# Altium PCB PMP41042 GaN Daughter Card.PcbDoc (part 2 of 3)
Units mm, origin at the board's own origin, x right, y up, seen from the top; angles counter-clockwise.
Board outline 43.43 x 37.33 mm, 6 copper layers (Top Layer, MidLayer1, MidLayer2, MidLayer3, MidLayer4, Bottom Layer), stack 1.844 mm thick; 57 components, 55 nets, 240 pads, 238 vias.
Unrouted connection lines stored in the file: 15.
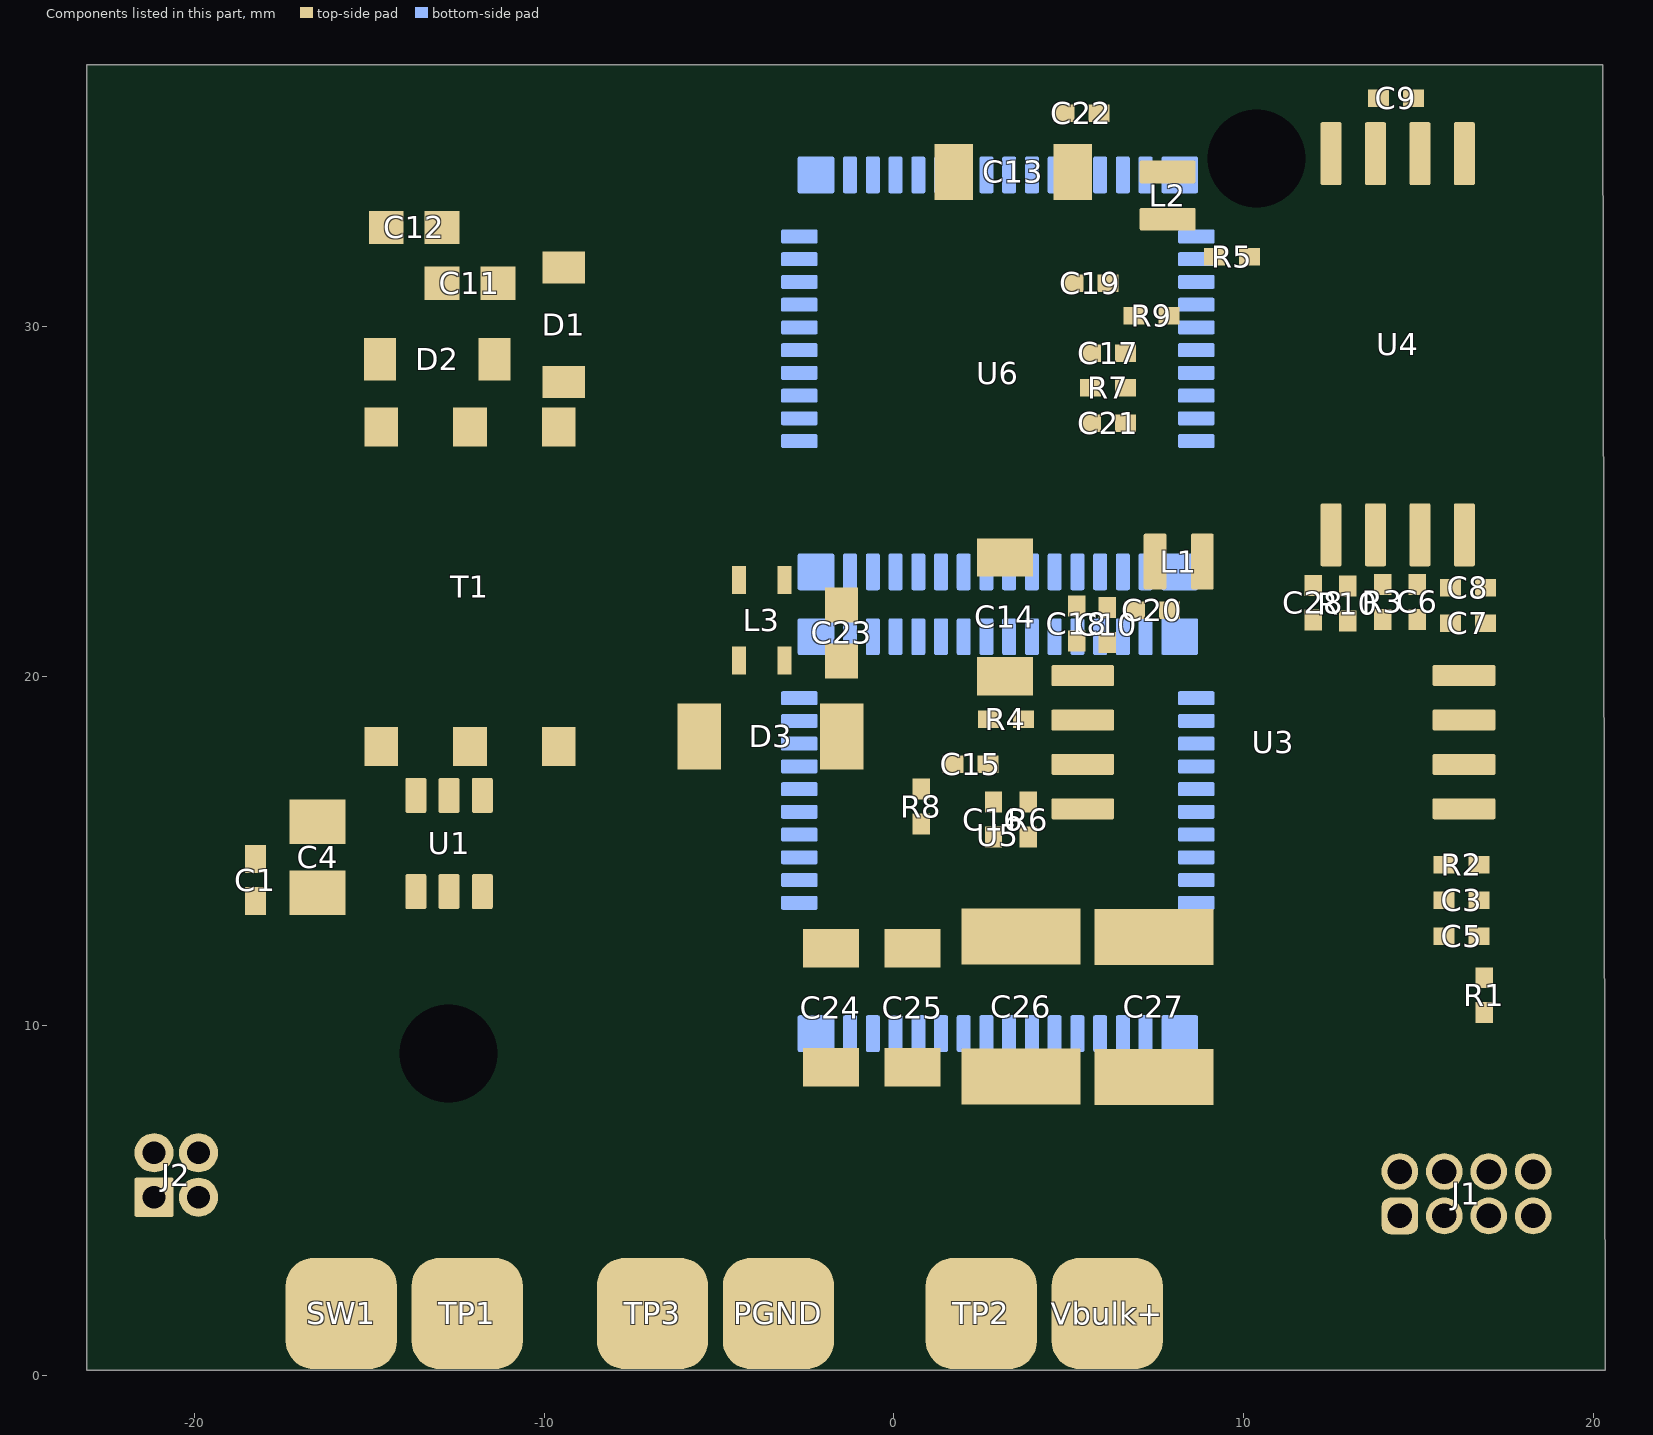
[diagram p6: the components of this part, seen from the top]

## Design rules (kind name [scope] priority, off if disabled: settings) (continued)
PolygonConnect PolygonConnect_46 [All vs IsNamedPolygon('PGND') Or  IsNamedPolygon('T200_4') Or  IsNamedPolygon('VBB') Or  IsNamedPolygon('SWNODE3') Or  IsNamedPolygon('LEG4_LS_DRV') Or  IsNamedPolygon('Iout_SNS') Or  IsNamedPolygon('SWNODE3') Or  IsNamedPolygon('T200_6') Or  IsNamedPolygon('SGND') Or  IsNamedPolygon('SIGNAL_LAYER_1_VBULK1_P106') Or  IsNamedPolygon('LEG3_HS_DRV') Or  IsNamedPolygon('TOP_LAYER_12VS_P126') Or  IsNamedPolygon('LEG4_HS_DRV') Or  IsNamedPolygon('SWNODE3') Or  IsNamedPolygon('SGND') Or  IsNamedPolygon('BOTTOM_LAYER_54V1_P128') Or  IsNamedPolygon('SGND') Or  IsNamedPolygon('Line') Or  IsNamedPolygon('TOP_LAYER_IOUT_SNS_P092') Or  IsNamedPolygon('C108_1') Or  IsNamedPolygon('D403_2') Or  IsNamedPolygon('SWNODE') Or  IsNamedPolygon('SIGNAL_LAYER_2_VBB_P094') Or  IsNamedPolygon('Vbulk') Or  IsNamedPolygon('D404_2') Or  IsNamedPolygon('VSR') Or  IsNamedPolygon('C108_1') Or  IsNamedPolygon('C108_1') Or  IsNamedPolygon('5Vp') Or  IsNamedPolygon('C108_1') Or  IsNamedPolygon('PGND') Or  IsNamedPolygon('D400_2') Or  IsNamedPolygon('SWNODE3') Or  IsNamedPolygon('Line') Or  IsNamedPolygon('C108_1') Or  IsNamedPolygon('TOP_LAYER_VBULK_P104') Or  IsNamedPolygon('Vbulk1') Or  IsNamedPolygon('T200_6') Or  IsNamedPolygon('T200_6') Or  IsNamedPolygon('SWNODE4') Or  IsNamedPolygon('C108_1') Or  IsNamedPolygon('D403_2') Or  IsNamedPolygon('PGND') Or  IsNamedPolygon('T200_4') Or  IsNamedPolygon('Line') Or  IsNamedPolygon('5Vs') Or  IsNamedPolygon('12Vp') Or  IsNamedPolygon('C102_1') Or  IsNamedPolygon('SGND') Or  IsNamedPolygon('TOP_LAYER_54V2_P048') Or  IsNamedPolygon('TOP_LAYER_54V1_P046') Or  IsNamedPolygon('SWNODE4') Or  IsNamedPolygon('ZCD') Or  IsNamedPolygon('SWNODE3') Or  IsNamedPolygon('SWNODE3') Or  IsNamedPolygon('BOTTOM_LAYER_NETC106_2_P030') Or  IsNamedPolygon('TOP_LAYER_54V2_P048') Or  IsNamedPolygon('T200_4') Or  IsNamedPolygon('SWNODE4') Or  IsNamedPolygon('SWNODE4') Or  IsNamedPolygon('SGND') Or  IsNamedPolygon('SGND') Or  IsNamedPolygon('SGND') Or  IsNamedPolygon('SWNODE4') Or  IsNamedPolygon('VSR') Or  IsNamedPolygon('SWNODE3') Or  IsNamedPolygon('SGND') Or  IsNamedPolygon('SGND') Or  IsNamedPolygon('SGND') Or  IsNamedPolygon('SGND') Or  IsNamedPolygon('SGND') Or  IsNamedPolygon('SGND') Or  IsNamedPolygon('BOTTOM_LAYER_54V1_P128') Or  IsNamedPolygon('SGND') Or  IsNamedPolygon('VSR') Or  IsNamedPolygon('C102_1') Or  IsNamedPolygon('C102_1') Or  IsNamedPolygon('C102_1') Or  IsNamedPolygon('C102_1') Or  IsNamedPolygon('C102_1') Or  IsNamedPolygon('ZCD') Or  IsNamedPolygon('PGND') Or  IsNamedPolygon('PGND') Or  IsNamedPolygon('Vbulk1') Or  IsNamedPolygon('Vbulk') Or  IsNamedPolygon('Vbulk1') Or  IsNamedPolygon('Vbulk1') Or  IsNamedPolygon('ZCD') Or  IsNamedPolygon('Neutral') Or  IsNamedPolygon('Neutral') Or  IsNamedPolygon('C106_2') Or  IsNamedPolygon('C106_2') Or  IsNamedPolygon('C106_2') Or  IsNamedPolygon('SWNODE') Or  IsNamedPolygon('Vbulk1') Or  IsNamedPolygon('Earth1') Or  IsNamedPolygon('Earth1') Or  IsNamedPolygon('Earth1') Or  IsNamedPolygon('Earth1') Or  IsNamedPolygon('Earth1') Or  IsNamedPolygon('Earth1') Or  IsNamedPolygon('ZCD') Or  IsNamedPolygon('VBB') Or  IsNamedPolygon('PGND') Or  IsNamedPolygon('D106_1') Or  IsNamedPolygon('PGND') Or  IsNamedPolygon('PGND') Or  IsNamedPolygon('D106_1') Or  IsNamedPolygon('Vbulk') Or  IsNamedPolygon('D106_1') Or  IsNamedPolygon('PGND') Or  IsNamedPolygon('VBB') Or  IsNamedPolygon('VBB') Or  IsNamedPolygon('PGND') Or  IsNamedPolygon('PGND') Or  IsNamedPolygon('PGND') Or  IsNamedPolygon('PGND') Or  IsNamedPolygon('PGND') Or  IsNamedPolygon('ZCD') Or  IsNamedPolygon('ZCD') Or  IsNamedPolygon('C412_2') Or  IsNamedPolygon('VBB') Or  IsNamedPolygon('PGND') Or  IsNamedPolygon('PGND') Or  IsNamedPolygon('PGND') Or  IsNamedPolygon('PGND') Or  IsNamedPolygon('PGND') Or  IsNamedPolygon('PGND') Or  IsNamedPolygon('PGND') Or  IsNamedPolygon('Vbulk') Or  IsNamedPolygon('D404_2') Or  IsNamedPolygon('PGND') Or  IsNamedPolygon('Iout_SNS') Or  IsNamedPolygon('54V2')] p14: connectstyle=Direct reliefconductorwidth=0.254 reliefentries=4 polygonreliefangle="90 Angle" airgapwidth=0.254
PolygonConnect PolygonConnect_45 [All vs IsNamedPolygon('Vbulk1') Or  IsNamedPolygon('TOP_LAYER_VBULK_P104') Or  IsNamedPolygon('SIGNAL_LAYER_1_VBULK1_P106') Or  IsNamedPolygon('Iout_SNS') Or  IsNamedPolygon('SIGNAL_LAYER_2_VBB_P094') Or  IsNamedPolygon('Line') Or  IsNamedPolygon('T200_4') Or  IsNamedPolygon('ZCD') Or  IsNamedPolygon('C108_1') Or  IsNamedPolygon('PGND') Or  IsNamedPolygon('BOTTOM_LAYER_NETC106_2_P030') Or  IsNamedPolygon('5Vp') Or  IsNamedPolygon('C108_1') Or  IsNamedPolygon('Line') Or  IsNamedPolygon('C102_1') Or  IsNamedPolygon('T200_4') Or  IsNamedPolygon('12Vp') Or  IsNamedPolygon('D403_2') Or  IsNamedPolygon('T200_6') Or  IsNamedPolygon('TOP_LAYER_54V1_P046') Or  IsNamedPolygon('TOP_LAYER_54V2_P048') Or  IsNamedPolygon('C108_1') Or  IsNamedPolygon('C108_1') Or  IsNamedPolygon('SWNODE3') Or  IsNamedPolygon('TOP_LAYER_54V2_P048') Or  IsNamedPolygon('PGND') Or  IsNamedPolygon('D403_2') Or  IsNamedPolygon('C108_1') Or  IsNamedPolygon('C108_1') Or  IsNamedPolygon('T200_6') Or  IsNamedPolygon('SGND') Or  IsNamedPolygon('SWNODE') Or  IsNamedPolygon('SGND') Or  IsNamedPolygon('SWNODE3') Or  IsNamedPolygon('BOTTOM_LAYER_54V1_P128') Or  IsNamedPolygon('C102_1') Or  IsNamedPolygon('SWNODE4') Or  IsNamedPolygon('C102_1') Or  IsNamedPolygon('SGND') Or  IsNamedPolygon('C102_1') Or  IsNamedPolygon('SGND') Or  IsNamedPolygon('VSR') Or  IsNamedPolygon('SGND') Or  IsNamedPolygon('SGND') Or  IsNamedPolygon('VSR') Or  IsNamedPolygon('SGND') Or  IsNamedPolygon('SWNODE4') Or  IsNamedPolygon('SGND') Or  IsNamedPolygon('SGND') Or  IsNamedPolygon('Vbulk1') Or  IsNamedPolygon('SGND') Or  IsNamedPolygon('PGND') Or  IsNamedPolygon('SGND') Or  IsNamedPolygon('PGND') Or  IsNamedPolygon('SWNODE3') Or  IsNamedPolygon('ZCD') Or  IsNamedPolygon('VSR') Or  IsNamedPolygon('C102_1') Or  IsNamedPolygon('SWNODE4') Or  IsNamedPolygon('C102_1') Or  IsNamedPolygon('SWNODE4') Or  IsNamedPolygon('SWNODE3') Or  IsNamedPolygon('PGND') Or  IsNamedPolygon('SGND') Or  IsNamedPolygon('D400_2') Or  IsNamedPolygon('SGND') Or  IsNamedPolygon('5Vs') Or  IsNamedPolygon('VBB') Or  IsNamedPolygon('T200_4') Or  IsNamedPolygon('T200_6') Or  IsNamedPolygon('SWNODE4') Or  IsNamedPolygon('LEG4_HS_DRV') Or  IsNamedPolygon('LEG4_LS_DRV') Or  IsNamedPolygon('LEG3_HS_DRV') Or  IsNamedPolygon('BOTTOM_LAYER_54V1_P128') Or  IsNamedPolygon('TOP_LAYER_12VS_P126') Or  IsNamedPolygon('Iout_SNS') Or  IsNamedPolygon('SWNODE3') Or  IsNamedPolygon('SWNODE3') Or  IsNamedPolygon('SWNODE3') Or  IsNamedPolygon('VBB') Or  IsNamedPolygon('Line') Or  IsNamedPolygon('D404_2') Or  IsNamedPolygon('SGND') Or  IsNamedPolygon('VBB') Or  IsNamedPolygon('VBB') Or  IsNamedPolygon('PGND') Or  IsNamedPolygon('PGND') Or  IsNamedPolygon('PGND') Or  IsNamedPolygon('PGND') Or  IsNamedPolygon('PGND') Or  IsNamedPolygon('ZCD') Or  IsNamedPolygon('ZCD') Or  IsNamedPolygon('C412_2') Or  IsNamedPolygon('VBB') Or  IsNamedPolygon('PGND') Or  IsNamedPolygon('PGND') Or  IsNamedPolygon('PGND') Or  IsNamedPolygon('PGND') Or  IsNamedPolygon('PGND') Or  IsNamedPolygon('PGND') Or  IsNamedPolygon('PGND') Or  IsNamedPolygon('VBB') Or  IsNamedPolygon('D404_2') Or  IsNamedPolygon('VBB') Or  IsNamedPolygon('Vbulk1') Or  IsNamedPolygon('Vbulk1') Or  IsNamedPolygon('ZCD') Or  IsNamedPolygon('Neutral') Or  IsNamedPolygon('Neutral') Or  IsNamedPolygon('C106_2') Or  IsNamedPolygon('C106_2') Or  IsNamedPolygon('C106_2') Or  IsNamedPolygon('SWNODE') Or  IsNamedPolygon('Vbulk1') Or  IsNamedPolygon('Earth1') Or  IsNamedPolygon('Earth1') Or  IsNamedPolygon('Earth1') Or  IsNamedPolygon('Earth1') Or  IsNamedPolygon('Earth1') Or  IsNamedPolygon('Earth1') Or  IsNamedPolygon('ZCD') Or  IsNamedPolygon('VBB') Or  IsNamedPolygon('PGND') Or  IsNamedPolygon('D106_1') Or  IsNamedPolygon('PGND') Or  IsNamedPolygon('PGND') Or  IsNamedPolygon('D106_1') Or  IsNamedPolygon('VBB') Or  IsNamedPolygon('D106_1') Or  IsNamedPolygon('PGND')] p15: connectstyle=Direct reliefconductorwidth=0.254 reliefentries=4 polygonreliefangle="90 Angle" airgapwidth=0.254
PolygonConnect PolygonConnect_44 [All vs IsNamedPolygon('Earth1') Or  IsNamedPolygon('Vbulk1') Or  IsNamedPolygon('Vbulk1') Or  IsNamedPolygon('VBB') Or  IsNamedPolygon('Vbulk1') Or  IsNamedPolygon('ZCD') Or  IsNamedPolygon('VBB') Or  IsNamedPolygon('PGND') Or  IsNamedPolygon('C412_2') Or  IsNamedPolygon('ZCD') Or  IsNamedPolygon('D106_1') Or  IsNamedPolygon('D106_1') Or  IsNamedPolygon('ZCD') Or  IsNamedPolygon('PGND') Or  IsNamedPolygon('PGND') Or  IsNamedPolygon('ZCD') Or  IsNamedPolygon('VBB') Or  IsNamedPolygon('PGND') Or  IsNamedPolygon('VBB') Or  IsNamedPolygon('PGND') Or  IsNamedPolygon('D106_1') Or  IsNamedPolygon('PGND') Or  IsNamedPolygon('PGND') Or  IsNamedPolygon('PGND') Or  IsNamedPolygon('VBB') Or  IsNamedPolygon('PGND') Or  IsNamedPolygon('PGND') Or  IsNamedPolygon('C102_1') Or  IsNamedPolygon('ZCD') Or  IsNamedPolygon('C102_1') Or  IsNamedPolygon('C102_1') Or  IsNamedPolygon('C102_1') Or  IsNamedPolygon('PGND') Or  IsNamedPolygon('C102_1') Or  IsNamedPolygon('Line') Or  IsNamedPolygon('T200_4') Or  IsNamedPolygon('T200_4') Or  IsNamedPolygon('SIGNAL_LAYER_1_VBULK1_P106') Or  IsNamedPolygon('TOP_LAYER_VBULK_P104') Or  IsNamedPolygon('T200_4') Or  IsNamedPolygon('SGND') Or  IsNamedPolygon('T200_6') Or  IsNamedPolygon('C108_1') Or  IsNamedPolygon('SWNODE3') Or  IsNamedPolygon('SWNODE') Or  IsNamedPolygon('SWNODE3') Or  IsNamedPolygon('LEG3_HS_DRV') Or  IsNamedPolygon('BOTTOM_LAYER_NETC106_2_P030') Or  IsNamedPolygon('C102_1') Or  IsNamedPolygon('SWNODE4') Or  IsNamedPolygon('SIGNAL_LAYER_2_VBB_P094') Or  IsNamedPolygon('SGND') Or  IsNamedPolygon('VSR') Or  IsNamedPolygon('C108_1') Or  IsNamedPolygon('BOTTOM_LAYER_54V1_P128') Or  IsNamedPolygon('TOP_LAYER_54V2_P048') Or  IsNamedPolygon('TOP_LAYER_54V1_P046') Or  IsNamedPolygon('C108_1') Or  IsNamedPolygon('D403_2') Or  IsNamedPolygon('ZCD') Or  IsNamedPolygon('PGND') Or  IsNamedPolygon('SWNODE3') Or  IsNamedPolygon('Line') Or  IsNamedPolygon('D400_2') Or  IsNamedPolygon('SGND') Or  IsNamedPolygon('PGND') Or  IsNamedPolygon('SGND') Or  IsNamedPolygon('LEG4_HS_DRV') Or  IsNamedPolygon('SWNODE3') Or  IsNamedPolygon('5Vs') Or  IsNamedPolygon('SWNODE4') Or  IsNamedPolygon('SGND') Or  IsNamedPolygon('SGND') Or  IsNamedPolygon('C108_1') Or  IsNamedPolygon('5Vp') Or  IsNamedPolygon('12Vp') Or  IsNamedPolygon('Iout_SNS') Or  IsNamedPolygon('D404_2') Or  IsNamedPolygon('SGND') Or  IsNamedPolygon('T200_6') Or  IsNamedPolygon('TOP_LAYER_54V2_P048') Or  IsNamedPolygon('SGND') Or  IsNamedPolygon('SWNODE3') Or  IsNamedPolygon('SWNODE4') Or  IsNamedPolygon('Iout_SNS') Or  IsNamedPolygon('C108_1') Or  IsNamedPolygon('BOTTOM_LAYER_54V1_P128') Or  IsNamedPolygon('SWNODE3') Or  IsNamedPolygon('LEG4_LS_DRV') Or  IsNamedPolygon('SGND') Or  IsNamedPolygon('SWNODE4') Or  IsNamedPolygon('T200_6') Or  IsNamedPolygon('TOP_LAYER_12VS_P126') Or  IsNamedPolygon('Line') Or  IsNamedPolygon('Vbulk1') Or  IsNamedPolygon('SWNODE3') Or  IsNamedPolygon('SGND') Or  IsNamedPolygon('VBB') Or  IsNamedPolygon('SGND') Or  IsNamedPolygon('SGND') Or  IsNamedPolygon('SWNODE4') Or  IsNamedPolygon('PGND') Or  IsNamedPolygon('D403_2') Or  IsNamedPolygon('VSR') Or  IsNamedPolygon('SGND') Or  IsNamedPolygon('SGND') Or  IsNamedPolygon('VBB') Or  IsNamedPolygon('C108_1') Or  IsNamedPolygon('Earth1') Or  IsNamedPolygon('Earth1') Or  IsNamedPolygon('VSR') Or  IsNamedPolygon('C106_2') Or  IsNamedPolygon('Vbulk1') Or  IsNamedPolygon('C106_2') Or  IsNamedPolygon('C106_2') Or  IsNamedPolygon('Earth1') Or  IsNamedPolygon('SWNODE') Or  IsNamedPolygon('Neutral') Or  IsNamedPolygon('Earth1') Or  IsNamedPolygon('Earth1') Or  IsNamedPolygon('Neutral')] p16: connectstyle=Direct reliefconductorwidth=0.254 reliefentries=4 polygonreliefangle="90 Angle" airgapwidth=0.254
PolygonConnect PolygonConnect_43 [All vs IsNamedPolygon('SWNODE') Or  IsNamedPolygon('D403_2') Or  IsNamedPolygon('D403_2') Or  IsNamedPolygon('PGND') Or  IsNamedPolygon('BOTTOM_LAYER_NETC106_2_P030') Or  IsNamedPolygon('C102_1') Or  IsNamedPolygon('SGND') Or  IsNamedPolygon('TOP_LAYER_54V1_P046') Or  IsNamedPolygon('TOP_LAYER_54V2_P048') Or  IsNamedPolygon('TOP_LAYER_54V2_P048') Or  IsNamedPolygon('C108_1') Or  IsNamedPolygon('C108_1') Or  IsNamedPolygon('C108_1') Or  IsNamedPolygon('C108_1') Or  IsNamedPolygon('C108_1') Or  IsNamedPolygon('C108_1') Or  IsNamedPolygon('PGND') Or  IsNamedPolygon('ZCD') Or  IsNamedPolygon('Line') Or  IsNamedPolygon('5Vp') Or  IsNamedPolygon('12Vp') Or  IsNamedPolygon('T200_4') Or  IsNamedPolygon('T200_6') Or  IsNamedPolygon('SWNODE3') Or  IsNamedPolygon('T200_4') Or  IsNamedPolygon('T200_6') Or  IsNamedPolygon('SWNODE4') Or  IsNamedPolygon('VSR') Or  IsNamedPolygon('Iout_SNS') Or  IsNamedPolygon('SIGNAL_LAYER_2_VBB_P094') Or  IsNamedPolygon('Vbulk1') Or  IsNamedPolygon('TOP_LAYER_VBULK_P104') Or  IsNamedPolygon('SIGNAL_LAYER_1_VBULK1_P106') Or  IsNamedPolygon('Line') Or  IsNamedPolygon('Line') Or  IsNamedPolygon('D404_2') Or  IsNamedPolygon('VBB') Or  IsNamedPolygon('D400_2') Or  IsNamedPolygon('SGND') Or  IsNamedPolygon('PGND') Or  IsNamedPolygon('TOP_LAYER_12VS_P126') Or  IsNamedPolygon('BOTTOM_LAYER_54V1_P128') Or  IsNamedPolygon('LEG3_HS_DRV') Or  IsNamedPolygon('LEG4_LS_DRV') Or  IsNamedPolygon('LEG4_HS_DRV') Or  IsNamedPolygon('SWNODE4') Or  IsNamedPolygon('SWNODE3') Or  IsNamedPolygon('T200_6') Or  IsNamedPolygon('T200_4') Or  IsNamedPolygon('VBB') Or  IsNamedPolygon('5Vs') Or  IsNamedPolygon('SGND') Or  IsNamedPolygon('Iout_SNS') Or  IsNamedPolygon('SGND') Or  IsNamedPolygon('SWNODE3') Or  IsNamedPolygon('SWNODE3') Or  IsNamedPolygon('SWNODE3') Or  IsNamedPolygon('SWNODE3') Or  IsNamedPolygon('SGND') Or  IsNamedPolygon('SGND') Or  IsNamedPolygon('SGND') Or  IsNamedPolygon('SWNODE4') Or  IsNamedPolygon('SWNODE4') Or  IsNamedPolygon('SWNODE4') Or  IsNamedPolygon('VSR') Or  IsNamedPolygon('SWNODE3') Or  IsNamedPolygon('SGND') Or  IsNamedPolygon('SGND') Or  IsNamedPolygon('SGND') Or  IsNamedPolygon('SGND') Or  IsNamedPolygon('SGND') Or  IsNamedPolygon('SGND') Or  IsNamedPolygon('BOTTOM_LAYER_54V1_P128') Or  IsNamedPolygon('SGND') Or  IsNamedPolygon('VSR') Or  IsNamedPolygon('C102_1') Or  IsNamedPolygon('C102_1') Or  IsNamedPolygon('C102_1') Or  IsNamedPolygon('C102_1') Or  IsNamedPolygon('C102_1') Or  IsNamedPolygon('ZCD') Or  IsNamedPolygon('PGND') Or  IsNamedPolygon('PGND') Or  IsNamedPolygon('Vbulk1') Or  IsNamedPolygon('VBB') Or  IsNamedPolygon('Vbulk1') Or  IsNamedPolygon('Vbulk1') Or  IsNamedPolygon('ZCD') Or  IsNamedPolygon('Neutral') Or  IsNamedPolygon('Neutral') Or  IsNamedPolygon('C106_2') Or  IsNamedPolygon('C106_2') Or  IsNamedPolygon('C106_2') Or  IsNamedPolygon('SWNODE') Or  IsNamedPolygon('Vbulk1') Or  IsNamedPolygon('Earth1') Or  IsNamedPolygon('Earth1') Or  IsNamedPolygon('Earth1') Or  IsNamedPolygon('Earth1') Or  IsNamedPolygon('Earth1') Or  IsNamedPolygon('Earth1') Or  IsNamedPolygon('ZCD') Or  IsNamedPolygon('VBB') Or  IsNamedPolygon('PGND') Or  IsNamedPolygon('D106_1') Or  IsNamedPolygon('PGND') Or  IsNamedPolygon('PGND') Or  IsNamedPolygon('D106_1') Or  IsNamedPolygon('VBB') Or  IsNamedPolygon('D106_1') Or  IsNamedPolygon('PGND') Or  IsNamedPolygon('VBB') Or  IsNamedPolygon('VBB') Or  IsNamedPolygon('PGND') Or  IsNamedPolygon('PGND') Or  IsNamedPolygon('PGND') Or  IsNamedPolygon('PGND') Or  IsNamedPolygon('PGND')] p17: connectstyle=Direct reliefconductorwidth=0.254 reliefentries=4 polygonreliefangle="90 Angle" airgapwidth=0.254
PolygonConnect PolygonConnect_42 [All vs IsNamedPolygon('Neutral') Or  IsNamedPolygon('Earth1') Or  IsNamedPolygon('Earth1') Or  IsNamedPolygon('D404_2') Or  IsNamedPolygon('Line') Or  IsNamedPolygon('SIGNAL_LAYER_1_VBULK1_P106') Or  IsNamedPolygon('Line') Or  IsNamedPolygon('C102_1') Or  IsNamedPolygon('SWNODE3') Or  IsNamedPolygon('SWNODE3') Or  IsNamedPolygon('SWNODE') Or  IsNamedPolygon('5Vp') Or  IsNamedPolygon('T200_6') Or  IsNamedPolygon('SWNODE3') Or  IsNamedPolygon('SGND') Or  IsNamedPolygon('SWNODE3') Or  IsNamedPolygon('VSR') Or  IsNamedPolygon('C108_1') Or  IsNamedPolygon('SWNODE3') Or  IsNamedPolygon('TOP_LAYER_12VS_P126') Or  IsNamedPolygon('SGND') Or  IsNamedPolygon('SGND') Or  IsNamedPolygon('SGND') Or  IsNamedPolygon('T200_6') Or  IsNamedPolygon('SWNODE4') Or  IsNamedPolygon('C108_1') Or  IsNamedPolygon('C106_2') Or  IsNamedPolygon('SGND') Or  IsNamedPolygon('Neutral') Or  IsNamedPolygon('SIGNAL_LAYER_2_VBB_P094') Or  IsNamedPolygon('Vbulk1') Or  IsNamedPolygon('SGND') Or  IsNamedPolygon('SGND') Or  IsNamedPolygon('TOP_LAYER_54V1_P046') Or  IsNamedPolygon('TOP_LAYER_54V2_P048') Or  IsNamedPolygon('TOP_LAYER_54V2_P048') Or  IsNamedPolygon('C102_1') Or  IsNamedPolygon('SGND') Or  IsNamedPolygon('T200_4') Or  IsNamedPolygon('12Vp') Or  IsNamedPolygon('SGND') Or  IsNamedPolygon('D400_2') Or  IsNamedPolygon('LEG3_HS_DRV') Or  IsNamedPolygon('LEG4_LS_DRV') Or  IsNamedPolygon('T200_4') Or  IsNamedPolygon('BOTTOM_LAYER_54V1_P128') Or  IsNamedPolygon('SGND') Or  IsNamedPolygon('VBB') Or  IsNamedPolygon('SWNODE4') Or  IsNamedPolygon('SWNODE4') Or  IsNamedPolygon('SWNODE4') Or  IsNamedPolygon('VSR') Or  IsNamedPolygon('Iout_SNS') Or  IsNamedPolygon('VBB') Or  IsNamedPolygon('PGND') Or  IsNamedPolygon('Line') Or  IsNamedPolygon('ZCD') Or  IsNamedPolygon('D403_2') Or  IsNamedPolygon('SWNODE3') Or  IsNamedPolygon('Vbulk1') Or  IsNamedPolygon('ZCD') Or  IsNamedPolygon('LEG4_HS_DRV') Or  IsNamedPolygon('BOTTOM_LAYER_54V1_P128') Or  IsNamedPolygon('VBB') Or  IsNamedPolygon('PGND') Or  IsNamedPolygon('ZCD') Or  IsNamedPolygon('ZCD') Or  IsNamedPolygon('Earth1') Or  IsNamedPolygon('VBB') Or  IsNamedPolygon('PGND') Or  IsNamedPolygon('PGND') Or  IsNamedPolygon('Vbulk1') Or  IsNamedPolygon('SWNODE') Or  IsNamedPolygon('C106_2') Or  IsNamedPolygon('C106_2') Or  IsNamedPolygon('C108_1') Or  IsNamedPolygon('SWNODE3') Or  IsNamedPolygon('SWNODE4') Or  IsNamedPolygon('Vbulk1') Or  IsNamedPolygon('SGND') Or  IsNamedPolygon('C102_1') Or  IsNamedPolygon('BOTTOM_LAYER_NETC106_2_P030') Or  IsNamedPolygon('Earth1') Or  IsNamedPolygon('Earth1') Or  IsNamedPolygon('Vbulk1') Or  IsNamedPolygon('Earth1') Or  IsNamedPolygon('T200_6') Or  IsNamedPolygon('T200_4') Or  IsNamedPolygon('C102_1') Or  IsNamedPolygon('C102_1') Or  IsNamedPolygon('C102_1') Or  IsNamedPolygon('VBB') Or  IsNamedPolygon('5Vs') Or  IsNamedPolygon('SGND') Or  IsNamedPolygon('Iout_SNS') Or  IsNamedPolygon('C108_1') Or  IsNamedPolygon('C108_1') Or  IsNamedPolygon('C108_1') Or  IsNamedPolygon('PGND') Or  IsNamedPolygon('D403_2') Or  IsNamedPolygon('PGND') Or  IsNamedPolygon('SGND') Or  IsNamedPolygon('SGND') Or  IsNamedPolygon('VSR')] p18: connectstyle=Direct reliefconductorwidth=0.254 reliefentries=4 polygonreliefangle="90 Angle" airgapwidth=0.254
PolygonConnect PolygonConnect_41 [All vs IsNamedPolygon('VBB') Or  IsNamedPolygon('SWNODE3') Or  IsNamedPolygon('T200_4') Or  IsNamedPolygon('Earth1') Or  IsNamedPolygon('BOTTOM_LAYER_54V1_P128') Or  IsNamedPolygon('SGND') Or  IsNamedPolygon('TOP_LAYER_12VS_P126') Or  IsNamedPolygon('C102_1') Or  IsNamedPolygon('VSR') Or  IsNamedPolygon('Earth1') Or  IsNamedPolygon('Neutral') Or  IsNamedPolygon('Vbulk1') Or  IsNamedPolygon('SWNODE4') Or  IsNamedPolygon('C106_2') Or  IsNamedPolygon('PGND') Or  IsNamedPolygon('SGND') Or  IsNamedPolygon('VBB') Or  IsNamedPolygon('PGND') Or  IsNamedPolygon('LEG4_LS_DRV') Or  IsNamedPolygon('C102_1') Or  IsNamedPolygon('SWNODE4') Or  IsNamedPolygon('C106_2') Or  IsNamedPolygon('Vbulk1') Or  IsNamedPolygon('C102_1') Or  IsNamedPolygon('BOTTOM_LAYER_54V1_P128') Or  IsNamedPolygon('LEG3_HS_DRV') Or  IsNamedPolygon('SGND') Or  IsNamedPolygon('SGND') Or  IsNamedPolygon('Earth1') Or  IsNamedPolygon('SGND') Or  IsNamedPolygon('SGND') Or  IsNamedPolygon('5Vs') Or  IsNamedPolygon('LEG4_HS_DRV') Or  IsNamedPolygon('Earth1') Or  IsNamedPolygon('SGND') Or  IsNamedPolygon('SWNODE3') Or  IsNamedPolygon('Iout_SNS') Or  IsNamedPolygon('ZCD') Or  IsNamedPolygon('Earth1') Or  IsNamedPolygon('VSR') Or  IsNamedPolygon('C102_1') Or  IsNamedPolygon('C102_1') Or  IsNamedPolygon('Vbulk1') Or  IsNamedPolygon('C106_2') Or  IsNamedPolygon('ZCD') Or  IsNamedPolygon('SWNODE3') Or  IsNamedPolygon('SWNODE3') Or  IsNamedPolygon('Vbulk1') Or  IsNamedPolygon('SWNODE4') Or  IsNamedPolygon('Neutral') Or  IsNamedPolygon('SWNODE3') Or  IsNamedPolygon('SWNODE4') Or  IsNamedPolygon('Earth1') Or  IsNamedPolygon('D400_2') Or  IsNamedPolygon('SGND') Or  IsNamedPolygon('SGND') Or  IsNamedPolygon('SGND') Or  IsNamedPolygon('SWNODE') Or  IsNamedPolygon('VSR') Or  IsNamedPolygon('SGND') Or  IsNamedPolygon('SIGNAL_LAYER_1_VBULK1_P106') Or  IsNamedPolygon('SGND') Or  IsNamedPolygon('T200_6') Or  IsNamedPolygon('SWNODE4') Or  IsNamedPolygon('VBB') Or  IsNamedPolygon('T200_6') Or  IsNamedPolygon('Line') Or  IsNamedPolygon('Iout_SNS') Or  IsNamedPolygon('Vbulk1') Or  IsNamedPolygon('VBB') Or  IsNamedPolygon('SIGNAL_LAYER_2_VBB_P094') Or  IsNamedPolygon('SGND') Or  IsNamedPolygon('D404_2') Or  IsNamedPolygon('SWNODE3') Or  IsNamedPolygon('Line') Or  IsNamedPolygon('PGND') Or  IsNamedPolygon('TOP_LAYER_54V2_P048') Or  IsNamedPolygon('TOP_LAYER_54V1_P046') Or  IsNamedPolygon('TOP_LAYER_54V2_P048') Or  IsNamedPolygon('C108_1') Or  IsNamedPolygon('BOTTOM_LAYER_NETC106_2_P030') Or  IsNamedPolygon('D403_2') Or  IsNamedPolygon('T200_4') Or  IsNamedPolygon('Line') Or  IsNamedPolygon('PGND') Or  IsNamedPolygon('SWNODE3') Or  IsNamedPolygon('ZCD') Or  IsNamedPolygon('SWNODE') Or  IsNamedPolygon('D403_2') Or  IsNamedPolygon('C108_1') Or  IsNamedPolygon('C102_1') Or  IsNamedPolygon('C108_1') Or  IsNamedPolygon('PGND') Or  IsNamedPolygon('C108_1') Or  IsNamedPolygon('C108_1') Or  IsNamedPolygon('5Vp') Or  IsNamedPolygon('T200_4') Or  IsNamedPolygon('12Vp') Or  IsNamedPolygon('T200_6') Or  IsNamedPolygon('C108_1') Or  IsNamedPolygon('SGND')] p19: connectstyle=Direct reliefconductorwidth=0.254 reliefentries=4 polygonreliefangle="90 Angle" airgapwidth=0.254
PolygonConnect PolygonConnect_40 [All vs IsNamedPolygon('Neutral')] p20: connectstyle=Direct reliefconductorwidth=0.254 reliefentries=4 polygonreliefangle="90 Angle" airgapwidth=0.254
PolygonConnect PolygonConnect_39 [All vs IsNamedPolygon('12Vp')] p21: connectstyle=Direct reliefconductorwidth=0.254 reliefentries=4 polygonreliefangle="90 Angle" airgapwidth=0.254
PolygonConnect PolygonConnect_38 [All vs IsNamedPolygon('SWNODE') Or  IsNamedPolygon('D403_2') Or  IsNamedPolygon('D403_2') Or  IsNamedPolygon('PGND') Or  IsNamedPolygon('BOTTOM_LAYER_NETC106_2_P030') Or  IsNamedPolygon('C102_1') Or  IsNamedPolygon('SGND') Or  IsNamedPolygon('TOP_LAYER_54V1_P046') Or  IsNamedPolygon('TOP_LAYER_54V2_P048') Or  IsNamedPolygon('TOP_LAYER_54V2_P048') Or  IsNamedPolygon('C108_1') Or  IsNamedPolygon('C108_1') Or  IsNamedPolygon('C108_1') Or  IsNamedPolygon('C108_1') Or  IsNamedPolygon('C108_1') Or  IsNamedPolygon('C108_1') Or  IsNamedPolygon('PGND') Or  IsNamedPolygon('ZCD') Or  IsNamedPolygon('Line') Or  IsNamedPolygon('5Vp') Or  IsNamedPolygon('12Vp') Or  IsNamedPolygon('T200_4') Or  IsNamedPolygon('T200_6') Or  IsNamedPolygon('SWNODE3') Or  IsNamedPolygon('T200_4') Or  IsNamedPolygon('T200_6') Or  IsNamedPolygon('SWNODE4') Or  IsNamedPolygon('VSR') Or  IsNamedPolygon('Iout_SNS') Or  IsNamedPolygon('SIGNAL_LAYER_2_VBB_P094') Or  IsNamedPolygon('Vbulk1') Or  IsNamedPolygon('VBB') Or  IsNamedPolygon('SIGNAL_LAYER_1_VBULK1_P106') Or  IsNamedPolygon('Line') Or  IsNamedPolygon('Line') Or  IsNamedPolygon('Line') Or  IsNamedPolygon('D404_2') Or  IsNamedPolygon('VBB') Or  IsNamedPolygon('D400_2') Or  IsNamedPolygon('SGND') Or  IsNamedPolygon('PGND') Or  IsNamedPolygon('TOP_LAYER_12VS_P126') Or  IsNamedPolygon('BOTTOM_LAYER_54V1_P128') Or  IsNamedPolygon('LEG3_HS_DRV') Or  IsNamedPolygon('LEG4_LS_DRV') Or  IsNamedPolygon('LEG4_HS_DRV') Or  IsNamedPolygon('SWNODE4') Or  IsNamedPolygon('SWNODE3') Or  IsNamedPolygon('T200_6') Or  IsNamedPolygon('T200_4') Or  IsNamedPolygon('VBB') Or  IsNamedPolygon('5Vs') Or  IsNamedPolygon('SGND') Or  IsNamedPolygon('Iout_SNS') Or  IsNamedPolygon('SGND') Or  IsNamedPolygon('SWNODE3') Or  IsNamedPolygon('SWNODE3') Or  IsNamedPolygon('SWNODE3') Or  IsNamedPolygon('SWNODE3') Or  IsNamedPolygon('SGND') Or  IsNamedPolygon('SGND') Or  IsNamedPolygon('SGND') Or  IsNamedPolygon('SWNODE4') Or  IsNamedPolygon('SWNODE4') Or  IsNamedPolygon('SWNODE4') Or  IsNamedPolygon('VSR') Or  IsNamedPolygon('SWNODE3') Or  IsNamedPolygon('SGND') Or  IsNamedPolygon('SGND') Or  IsNamedPolygon('SGND') Or  IsNamedPolygon('SGND') Or  IsNamedPolygon('SGND') Or  IsNamedPolygon('SGND') Or  IsNamedPolygon('BOTTOM_LAYER_54V1_P128') Or  IsNamedPolygon('SGND') Or  IsNamedPolygon('VSR') Or  IsNamedPolygon('C102_1') Or  IsNamedPolygon('C102_1') Or  IsNamedPolygon('C102_1') Or  IsNamedPolygon('C102_1') Or  IsNamedPolygon('C102_1') Or  IsNamedPolygon('ZCD') Or  IsNamedPolygon('PGND') Or  IsNamedPolygon('PGND') Or  IsNamedPolygon('Vbulk1') Or  IsNamedPolygon('VBB') Or  IsNamedPolygon('Vbulk1') Or  IsNamedPolygon('Vbulk1') Or  IsNamedPolygon('ZCD') Or  IsNamedPolygon('Neutral') Or  IsNamedPolygon('Neutral')] p22: connectstyle=Direct reliefconductorwidth=0.254 reliefentries=4 polygonreliefangle="90 Angle" airgapwidth=0.254
PolygonConnect PolygonConnect_37 [All vs IsNamedPolygon('SGND') Or  IsNamedPolygon('SWNODE4') Or  IsNamedPolygon('5Vp') Or  IsNamedPolygon('SWNODE4') Or  IsNamedPolygon('VBB') Or  IsNamedPolygon('Line') Or  IsNamedPolygon('SGND') Or  IsNamedPolygon('SIGNAL_LAYER_2_C102_1_P032') Or  IsNamedPolygon('TOP_LAYER_54V2_P048') Or  IsNamedPolygon('ZCD') Or  IsNamedPolygon('PGND') Or  IsNamedPolygon('SIGNAL_LAYER_2_VBB_P094') Or  IsNamedPolygon('Line') Or  IsNamedPolygon('Line') Or  IsNamedPolygon('D404_2') Or  IsNamedPolygon('PGND') Or  IsNamedPolygon('SIGNAL_LAYER_1_ZCD_P108') Or  IsNamedPolygon('SWNODE3') Or  IsNamedPolygon('SIGNAL_LAYER_4_C102_1_P038') Or  IsNamedPolygon('SWNODE3') Or  IsNamedPolygon('LEG4_HS_DRV') Or  IsNamedPolygon('SWNODE4') Or  IsNamedPolygon('5Vs') Or  IsNamedPolygon('VBB') Or  IsNamedPolygon('TOP_LAYER_54V2_P048') Or  IsNamedPolygon('C102_1') Or  IsNamedPolygon('LEG4_LS_DRV') Or  IsNamedPolygon('T200_4') Or  IsNamedPolygon('SWNODE3') Or  IsNamedPolygon('Line') Or  IsNamedPolygon('SGND') Or  IsNamedPolygon('SGND') Or  IsNamedPolygon('SWNODE4') Or  IsNamedPolygon('12Vp') Or  IsNamedPolygon('BOTTOM_LAYER_NETC106_2_P030') Or  IsNamedPolygon('T200_4') Or  IsNamedPolygon('Vbulk1') Or  IsNamedPolygon('C108_1') Or  IsNamedPolygon('BOTTOM_LAYER_54V1_P128') Or  IsNamedPolygon('BOTTOM_LAYER_54V1_P128') Or  IsNamedPolygon('SWNODE') Or  IsNamedPolygon('Iout_SNS') Or  IsNamedPolygon('VSR') Or  IsNamedPolygon('D400_2') Or  IsNamedPolygon('D403_2') Or  IsNamedPolygon('SWNODE3') Or  IsNamedPolygon('T200_6') Or  IsNamedPolygon('SWNODE3') Or  IsNamedPolygon('C108_1') Or  IsNamedPolygon('PGND') Or  IsNamedPolygon('BOTTOM_LAYER_VBULK1_P096') Or  IsNamedPolygon('BOTTOM_LAYER_54V1_P128') Or  IsNamedPolygon('TOP_LAYER_12VS_P126') Or  IsNamedPolygon('SIGNAL_LAYER_1_VBULK1_P106') Or  IsNamedPolygon('T200_4') Or  IsNamedPolygon('SGND') Or  IsNamedPolygon('C108_1') Or  IsNamedPolygon('SWNODE3') Or  IsNamedPolygon('T200_6') Or  IsNamedPolygon('T200_6') Or  IsNamedPolygon('T200_6') Or  IsNamedPolygon('SGND') Or  IsNamedPolygon('C108_1') Or  IsNamedPolygon('SGND') Or  IsNamedPolygon('VBB') Or  IsNamedPolygon('T200_4') Or  IsNamedPolygon('LEG3_HS_DRV') Or  IsNamedPolygon('C108_1') Or  IsNamedPolygon('D403_2') Or  IsNamedPolygon('Iout_SNS') Or  IsNamedPolygon('C108_1') Or  IsNamedPolygon('SWNODE4')] p23: connectstyle=Direct reliefconductorwidth=0.254 reliefentries=4 polygonreliefangle="90 Angle" airgapwidth=0.254
PolygonConnect PolygonConnect_36 [All vs IsNamedPolygon('PGND') Or  IsNamedPolygon('BOTTOM_LAYER_54V1_P128') Or  IsNamedPolygon('SGND') Or  IsNamedPolygon('LEG4_LS_DRV') Or  IsNamedPolygon('TOP_LAYER_12VS_P126') Or  IsNamedPolygon('LEG4_HS_DRV') Or  IsNamedPolygon('LEG3_HS_DRV') Or  IsNamedPolygon('SGND') Or  IsNamedPolygon('C108_1') Or  IsNamedPolygon('12Vp') Or  IsNamedPolygon('D403_2') Or  IsNamedPolygon('SIGNAL_LAYER_1_ZCD_P108') Or  IsNamedPolygon('C108_1') Or  IsNamedPolygon('BOTTOM_LAYER_VBULK1_P096') Or  IsNamedPolygon('SWNODE') Or  IsNamedPolygon('T200_4') Or  IsNamedPolygon('D400_2') Or  IsNamedPolygon('C102_1') Or  IsNamedPolygon('Line') Or  IsNamedPolygon('VBB') Or  IsNamedPolygon('Line') Or  IsNamedPolygon('TOP_LAYER_54V2_P048') Or  IsNamedPolygon('BOTTOM_LAYER_NETC106_2_P030') Or  IsNamedPolygon('SIGNAL_LAYER_1_VBULK1_P106') Or  IsNamedPolygon('Line') Or  IsNamedPolygon('5Vp') Or  IsNamedPolygon('BOTTOM_LAYER_54V1_P128') Or  IsNamedPolygon('D404_2') Or  IsNamedPolygon('C108_1') Or  IsNamedPolygon('VSR') Or  IsNamedPolygon('T200_6') Or  IsNamedPolygon('VBB') Or  IsNamedPolygon('C108_1') Or  IsNamedPolygon('SIGNAL_LAYER_2_C102_1_P032') Or  IsNamedPolygon('SGND') Or  IsNamedPolygon('PGND') Or  IsNamedPolygon('SIGNAL_LAYER_4_C102_1_P038') Or  IsNamedPolygon('Vbulk1') Or  IsNamedPolygon('TOP_LAYER_54V2_P048') Or  IsNamedPolygon('Iout_SNS') Or  IsNamedPolygon('PGND') Or  IsNamedPolygon('T200_4') Or  IsNamedPolygon('ZCD') Or  IsNamedPolygon('Line') Or  IsNamedPolygon('C108_1') Or  IsNamedPolygon('D403_2') Or  IsNamedPolygon('SIGNAL_LAYER_2_VBB_P094') Or  IsNamedPolygon('SGND') Or  IsNamedPolygon('C108_1') Or  IsNamedPolygon('SIGNAL_LAYER_1_IOUT_SNS_P044') Or  IsNamedPolygon('BOTTOM_LAYER_54V1_P128') Or  IsNamedPolygon('T200_6')] p24: connectstyle=Direct reliefconductorwidth=0.254 reliefentries=4 polygonreliefangle="90 Angle" airgapwidth=0.254
PolygonConnect PolygonConnect_35 [All vs IsNamedPolygon('SWNODE') Or  IsNamedPolygon('D403_2') Or  IsNamedPolygon('D403_2') Or  IsNamedPolygon('PGND') Or  IsNamedPolygon('BOTTOM_LAYER_NETC106_2_P030') Or  IsNamedPolygon('SIGNAL_LAYER_2_C102_1_P032') Or  IsNamedPolygon('C102_1') Or  IsNamedPolygon('SIGNAL_LAYER_4_C102_1_P038') Or  IsNamedPolygon('SGND') Or  IsNamedPolygon('SIGNAL_LAYER_1_IOUT_SNS_P044') Or  IsNamedPolygon('BOTTOM_LAYER_54V1_P128') Or  IsNamedPolygon('TOP_LAYER_54V2_P048') Or  IsNamedPolygon('BOTTOM_LAYER_54V1_P128') Or  IsNamedPolygon('TOP_LAYER_54V2_P048') Or  IsNamedPolygon('C108_1') Or  IsNamedPolygon('C108_1') Or  IsNamedPolygon('C108_1') Or  IsNamedPolygon('C108_1') Or  IsNamedPolygon('C108_1') Or  IsNamedPolygon('C108_1') Or  IsNamedPolygon('PGND') Or  IsNamedPolygon('ZCD') Or  IsNamedPolygon('Line') Or  IsNamedPolygon('5Vp') Or  IsNamedPolygon('12Vp') Or  IsNamedPolygon('T200_4') Or  IsNamedPolygon('T200_6') Or  IsNamedPolygon('SGND') Or  IsNamedPolygon('T200_4') Or  IsNamedPolygon('T200_6') Or  IsNamedPolygon('SGND') Or  IsNamedPolygon('VSR') Or  IsNamedPolygon('Iout_SNS') Or  IsNamedPolygon('SIGNAL_LAYER_2_VBB_P094') Or  IsNamedPolygon('BOTTOM_LAYER_VBULK1_P096') Or  IsNamedPolygon('Vbulk1') Or  IsNamedPolygon('VBB') Or  IsNamedPolygon('SIGNAL_LAYER_1_VBULK1_P106') Or  IsNamedPolygon('SIGNAL_LAYER_1_ZCD_P108') Or  IsNamedPolygon('Line') Or  IsNamedPolygon('Line') Or  IsNamedPolygon('Line') Or  IsNamedPolygon('D404_2') Or  IsNamedPolygon('VBB') Or  IsNamedPolygon('D400_2') Or  IsNamedPolygon('SGND') Or  IsNamedPolygon('PGND') Or  IsNamedPolygon('TOP_LAYER_12VS_P126') Or  IsNamedPolygon('BOTTOM_LAYER_54V1_P128') Or  IsNamedPolygon('LEG3_HS_DRV')] p25: connectstyle=Direct reliefconductorwidth=0.254 reliefentries=4 polygonreliefangle="90 Angle" airgapwidth=0.254
PolygonConnect PolygonConnect_34 [All vs IsNamedPolygon('SWNODE') Or  IsNamedPolygon('D403_2') Or  IsNamedPolygon('D403_2') Or  IsNamedPolygon('PGND') Or  IsNamedPolygon('BOTTOM_LAYER_NETC106_2_P030') Or  IsNamedPolygon('SIGNAL_LAYER_2_C102_1_P032') Or  IsNamedPolygon('C102_1') Or  IsNamedPolygon('SIGNAL_LAYER_4_C102_1_P038') Or  IsNamedPolygon('SGND') Or  IsNamedPolygon('SIGNAL_LAYER_1_IOUT_SNS_P044') Or  IsNamedPolygon('BOTTOM_LAYER_54V1_P128') Or  IsNamedPolygon('TOP_LAYER_54V2_P048') Or  IsNamedPolygon('BOTTOM_LAYER_54V1_P128') Or  IsNamedPolygon('TOP_LAYER_54V2_P048') Or  IsNamedPolygon('C108_1') Or  IsNamedPolygon('C108_1') Or  IsNamedPolygon('C108_1') Or  IsNamedPolygon('C108_1') Or  IsNamedPolygon('C108_1') Or  IsNamedPolygon('C108_1') Or  IsNamedPolygon('PGND') Or  IsNamedPolygon('ZCD') Or  IsNamedPolygon('Line') Or  IsNamedPolygon('5Vp') Or  IsNamedPolygon('12Vp') Or  IsNamedPolygon('T200_4') Or  IsNamedPolygon('T200_6') Or  IsNamedPolygon('SGND') Or  IsNamedPolygon('T200_4') Or  IsNamedPolygon('T200_6') Or  IsNamedPolygon('SGND') Or  IsNamedPolygon('VSR') Or  IsNamedPolygon('Iout_SNS') Or  IsNamedPolygon('SIGNAL_LAYER_2_VBB_P094') Or  IsNamedPolygon('BOTTOM_LAYER_VBULK1_P096') Or  IsNamedPolygon('Vbulk1') Or  IsNamedPolygon('VBB') Or  IsNamedPolygon('SIGNAL_LAYER_1_VBULK1_P106') Or  IsNamedPolygon('SIGNAL_LAYER_1_ZCD_P108') Or  IsNamedPolygon('Line') Or  IsNamedPolygon('Line') Or  IsNamedPolygon('Line') Or  IsNamedPolygon('D404_2') Or  IsNamedPolygon('VBB') Or  IsNamedPolygon('D400_2') Or  IsNamedPolygon('SGND')] p26: connectstyle=Direct reliefconductorwidth=0.254 reliefentries=4 polygonreliefangle="90 Angle" airgapwidth=0.254
PolygonConnect PolygonConnect_33 [All vs IsNamedPolygon('SIGNAL_LAYER_1_VBULK1_P106')] p27: connectstyle=Direct reliefconductorwidth=0.254 reliefentries=4 polygonreliefangle="90 Angle" airgapwidth=0.254
PolygonConnect PolygonConnect_32 [All vs IsNamedPolygon('SIGNAL_LAYER_1_VBULK1_P106')] p28: connectstyle=Direct reliefconductorwidth=0.254 reliefentries=4 polygonreliefangle="90 Angle" airgapwidth=0.254
PolygonConnect PolygonConnect_31 [All vs IsNamedPolygon('SIGNAL_LAYER_1_VBULK1_P106')] p29: connectstyle=Direct reliefconductorwidth=0.254 reliefentries=4 polygonreliefangle="90 Angle" airgapwidth=0.254
PolygonConnect PolygonConnect_30 [All vs IsNamedPolygon('VBB')] p30: connectstyle=Direct reliefconductorwidth=0.254 reliefentries=4 polygonreliefangle="90 Angle" airgapwidth=0.254
PolygonConnect PolygonConnect_29 [All vs IsNamedPolygon('SGND')] p31: connectstyle=Direct reliefconductorwidth=0.254 reliefentries=4 polygonreliefangle="90 Angle" airgapwidth=0.254
PolygonConnect PolygonConnect_28 [All vs IsNamedPolygon('Vbulk1')] p32: connectstyle=Direct reliefconductorwidth=0.254 reliefentries=4 polygonreliefangle="90 Angle" airgapwidth=0.254
PolygonConnect PolygonConnect_27 [All vs IsNamedPolygon('BOTTOM_LAYER_VBULK1_P096')] p33: connectstyle=Direct reliefconductorwidth=0.254 reliefentries=4 polygonreliefangle="90 Angle" airgapwidth=0.254
PolygonConnect PolygonConnect_26 [All vs IsNamedPolygon('SIGNAL_LAYER_2_VBB_P094')] p34: connectstyle=Direct reliefconductorwidth=0.254 reliefentries=4 polygonreliefangle="90 Angle" airgapwidth=0.254
PolygonConnect PolygonConnect_25 [All vs IsNamedPolygon('C108_1')] p35: connectstyle=Direct reliefconductorwidth=0.254 reliefentries=4 polygonreliefangle="90 Angle" airgapwidth=0.254
PolygonConnect PolygonConnect_24 [All vs IsNamedPolygon('BOTTOM_LAYER_EARTH_P100')] p36: connectstyle=Direct reliefconductorwidth=0.254 reliefentries=4 polygonreliefangle="90 Angle" airgapwidth=0.254
PolygonConnect PolygonConnect_23 [All vs IsNamedPolygon('BOTTOM_LAYER_54V1_P128')] p37: connectstyle=Direct reliefconductorwidth=0.254 reliefentries=4 polygonreliefangle="90 Angle" airgapwidth=0.254
PolygonConnect PolygonConnect_22 [All vs IsNamedPolygon('BOTTOM_LAYER_VBULK1_P096')] p38: connectstyle=Direct reliefconductorwidth=0.254 reliefentries=4 polygonreliefangle="90 Angle" airgapwidth=0.254
PolygonConnect PolygonConnect_21 [All vs IsNamedPolygon('SIGNAL_LAYER_2_VBB_P094')] p39: connectstyle=Direct reliefconductorwidth=0.254 reliefentries=4 polygonreliefangle="90 Angle" airgapwidth=0.254
PolygonConnect PolygonConnect_20 [All vs IsNamedPolygon('Iout_SNS')] p40: connectstyle=Direct reliefconductorwidth=0.254 reliefentries=4 polygonreliefangle="90 Angle" airgapwidth=0.254
PolygonConnect PolygonConnect_19 [All vs IsNamedPolygon('C108_1') Or  IsNamedPolygon('BOTTOM_LAYER_NETC106_2_P030') Or  IsNamedPolygon('D403_2') Or  IsNamedPolygon('C102_1') Or  IsNamedPolygon('SWNODE') Or  IsNamedPolygon('D403_2') Or  IsNamedPolygon('SIGNAL_LAYER_4_C102_1_P038') Or  IsNamedPolygon('PGND') Or  IsNamedPolygon('SIGNAL_LAYER_2_C102_1_P032') Or  IsNamedPolygon('SIGNAL_LAYER_1_IOUT_SNS_P044') Or  IsNamedPolygon('SGND') Or  IsNamedPolygon('C108_1') Or  IsNamedPolygon('BOTTOM_LAYER_54V1_P128') Or  IsNamedPolygon('C108_1') Or  IsNamedPolygon('C108_1') Or  IsNamedPolygon('TOP_LAYER_54V2_P048') Or  IsNamedPolygon('BOTTOM_LAYER_54V1_P128') Or  IsNamedPolygon('TOP_LAYER_54V2_P048') Or  IsNamedPolygon('C108_1') Or  IsNamedPolygon('C108_1') Or  IsNamedPolygon('12Vp') Or  IsNamedPolygon('5Vp') Or  IsNamedPolygon('Line') Or  IsNamedPolygon('T200_4') Or  IsNamedPolygon('SGND') Or  IsNamedPolygon('VSR') Or  IsNamedPolygon('ZCD') Or  IsNamedPolygon('PGND') Or  IsNamedPolygon('T200_6') Or  IsNamedPolygon('Neutral') Or  IsNamedPolygon('T200_4') Or  IsNamedPolygon('SGND') Or  IsNamedPolygon('T200_6')] p41: connectstyle=Direct reliefconductorwidth=0.254 reliefentries=4 polygonreliefangle="90 Angle" airgapwidth=0.254
PolygonConnect PolygonConnect_18 [All vs IsNamedPolygon('SWNODE') Or  IsNamedPolygon('D403_2') Or  IsNamedPolygon('D403_2') Or  IsNamedPolygon('PGND') Or  IsNamedPolygon('BOTTOM_LAYER_NETC106_2_P030') Or  IsNamedPolygon('SIGNAL_LAYER_2_C102_1_P032') Or  IsNamedPolygon('C102_1') Or  IsNamedPolygon('SIGNAL_LAYER_4_C102_1_P038') Or  IsNamedPolygon('SGND') Or  IsNamedPolygon('SIGNAL_LAYER_1_IOUT_SNS_P044') Or  IsNamedPolygon('BOTTOM_LAYER_54V1_P128') Or  IsNamedPolygon('TOP_LAYER_54V2_P048') Or  IsNamedPolygon('BOTTOM_LAYER_54V1_P128') Or  IsNamedPolygon('TOP_LAYER_54V2_P048') Or  IsNamedPolygon('C108_1') Or  IsNamedPolygon('C108_1') Or  IsNamedPolygon('C108_1') Or  IsNamedPolygon('C108_1') Or  IsNamedPolygon('C108_1') Or  IsNamedPolygon('C108_1') Or  IsNamedPolygon('Neutral') Or  IsNamedPolygon('PGND') Or  IsNamedPolygon('ZCD') Or  IsNamedPolygon('Line') Or  IsNamedPolygon('5Vp') Or  IsNamedPolygon('12Vp') Or  IsNamedPolygon('T200_4') Or  IsNamedPolygon('T200_6') Or  IsNamedPolygon('SGND') Or  IsNamedPolygon('T200_4') Or  IsNamedPolygon('T200_6') Or  IsNamedPolygon('SGND')] p42: connectstyle=Direct reliefconductorwidth=0.254 reliefentries=4 polygonreliefangle="90 Angle" airgapwidth=0.254
PolygonConnect PolygonConnect_17 [All vs IsNamedPolygon('12Vp') Or  IsNamedPolygon('T200_4') Or  IsNamedPolygon('T200_6') Or  IsNamedPolygon('SGND') Or  IsNamedPolygon('TOP_LAYER_54V2_P048') Or  IsNamedPolygon('SIGNAL_LAYER_1_IOUT_SNS_P044') Or  IsNamedPolygon('BOTTOM_LAYER_54V1_P128') Or  IsNamedPolygon('SGND') Or  IsNamedPolygon('C102_1') Or  IsNamedPolygon('SIGNAL_LAYER_4_C102_1_P038') Or  IsNamedPolygon('Neutral') Or  IsNamedPolygon('C108_1') Or  IsNamedPolygon('C108_1') Or  IsNamedPolygon('C108_1') Or  IsNamedPolygon('BOTTOM_LAYER_54V1_P128') Or  IsNamedPolygon('TOP_LAYER_54V2_P048') Or  IsNamedPolygon('SIGNAL_LAYER_2_C102_1_P032') Or  IsNamedPolygon('SWNODE') Or  IsNamedPolygon('C108_1') Or  IsNamedPolygon('C108_1') Or  IsNamedPolygon('C108_1') Or  IsNamedPolygon('D403_2') Or  IsNamedPolygon('BOTTOM_LAYER_NETC106_2_P030') Or  IsNamedPolygon('PGND') Or  IsNamedPolygon('D403_2') Or  IsNamedPolygon('5Vp') Or  IsNamedPolygon('PGND') Or  IsNamedPolygon('ZCD') Or  IsNamedPolygon('Line')] p43: connectstyle=Direct reliefconductorwidth=0.254 reliefentries=4 polygonreliefangle="90 Angle" airgapwidth=0.254
PolygonConnect PolygonConnect_16 [All vs IsNamedPolygon('D403_2') Or  IsNamedPolygon('C102_1') Or  IsNamedPolygon('C108_1') Or  IsNamedPolygon('SWNODE') Or  IsNamedPolygon('BOTTOM_LAYER_54V1_P128') Or  IsNamedPolygon('SGND') Or  IsNamedPolygon('Line') Or  IsNamedPolygon('ZCD') Or  IsNamedPolygon('SIGNAL_LAYER_1_IOUT_SNS_P044') Or  IsNamedPolygon('Neutral') Or  IsNamedPolygon('PGND') Or  IsNamedPolygon('12Vp') Or  IsNamedPolygon('C108_1') Or  IsNamedPolygon('C108_1') Or  IsNamedPolygon('TOP_LAYER_54V2_P048') Or  IsNamedPolygon('C108_1') Or  IsNamedPolygon('TOP_LAYER_54V2_P048') Or  IsNamedPolygon('T200_4') Or  IsNamedPolygon('T200_6') Or  IsNamedPolygon('D403_2') Or  IsNamedPolygon('C108_1') Or  IsNamedPolygon('C108_1') Or  IsNamedPolygon('SIGNAL_LAYER_4_C102_1_P038') Or  IsNamedPolygon('SIGNAL_LAYER_2_C102_1_P032') Or  IsNamedPolygon('PGND') Or  IsNamedPolygon('BOTTOM_LAYER_NETC106_2_P030') Or  IsNamedPolygon('5Vp') Or  IsNamedPolygon('BOTTOM_LAYER_54V1_P128')] p44: connectstyle=Direct reliefconductorwidth=0.254 reliefentries=4 polygonreliefangle="90 Angle" airgapwidth=0.254
PolygonConnect PolygonConnect_15 [All vs IsNamedPolygon('SWNODE') Or  IsNamedPolygon('D403_2') Or  IsNamedPolygon('D403_2') Or  IsNamedPolygon('SIGNAL_LAYER_1_PGND_P018') Or  IsNamedPolygon('PGND') Or  IsNamedPolygon('BOTTOM_LAYER_NETC106_2_P030') Or  IsNamedPolygon('SIGNAL_LAYER_2_C102_1_P032') Or  IsNamedPolygon('C102_1') Or  IsNamedPolygon('SIGNAL_LAYER_4_C102_1_P038') Or  IsNamedPolygon('SGND') Or  IsNamedPolygon('SIGNAL_LAYER_1_IOUT_SNS_P044') Or  IsNamedPolygon('BOTTOM_LAYER_54V1_P128') Or  IsNamedPolygon('TOP_LAYER_54V2_P048') Or  IsNamedPolygon('BOTTOM_LAYER_54V1_P128') Or  IsNamedPolygon('TOP_LAYER_54V2_P048') Or  IsNamedPolygon('C108_1') Or  IsNamedPolygon('C108_1') Or  IsNamedPolygon('C108_1') Or  IsNamedPolygon('C108_1') Or  IsNamedPolygon('C108_1') Or  IsNamedPolygon('C108_1') Or  IsNamedPolygon('Neutral') Or  IsNamedPolygon('PGND') Or  IsNamedPolygon('ZCD') Or  IsNamedPolygon('Line') Or  IsNamedPolygon('5Vp') Or  IsNamedPolygon('12Vp')] p45: connectstyle=Direct reliefconductorwidth=0.254 reliefentries=4 polygonreliefangle="90 Angle" airgapwidth=0.254
PolygonConnect PolygonConnect_14 [All vs IsNamedPolygon('TOP_LAYER_54V2_P048') Or  IsNamedPolygon('C108_1') Or  IsNamedPolygon('C108_1') Or  IsNamedPolygon('SIGNAL_LAYER_4_C102_1_P038') Or  IsNamedPolygon('C102_1') Or  IsNamedPolygon('SIGNAL_LAYER_2_C102_1_P032') Or  IsNamedPolygon('SIGNAL_LAYER_1_PGND_P018') Or  IsNamedPolygon('SIGNAL_LAYER_1_IOUT_SNS_P044') Or  IsNamedPolygon('SGND') Or  IsNamedPolygon('C108_1') Or  IsNamedPolygon('ZCD') Or  IsNamedPolygon('PGND') Or  IsNamedPolygon('TOP_LAYER_54V2_P048') Or  IsNamedPolygon('BOTTOM_LAYER_NETC106_2_P030') Or  IsNamedPolygon('PGND') Or  IsNamedPolygon('C108_1') Or  IsNamedPolygon('C108_1') Or  IsNamedPolygon('D403_2') Or  IsNamedPolygon('Line') Or  IsNamedPolygon('C108_1') Or  IsNamedPolygon('Neutral') Or  IsNamedPolygon('SWNODE') Or  IsNamedPolygon('D403_2') Or  IsNamedPolygon('BOTTOM_LAYER_54V1_P128') Or  IsNamedPolygon('BOTTOM_LAYER_54V1_P128')] p46: connectstyle=Direct reliefconductorwidth=0.254 reliefentries=4 polygonreliefangle="90 Angle" airgapwidth=0.254
PolygonConnect PolygonConnect_13 [All vs IsNamedPolygon('PGND') Or  IsNamedPolygon('D403_2') Or  IsNamedPolygon('SIGNAL_LAYER_1_PGND_P018') Or  IsNamedPolygon('D403_2') Or  IsNamedPolygon('SWNODE') Or  IsNamedPolygon('SGND') Or  IsNamedPolygon('BOTTOM_LAYER_54V1_P128') Or  IsNamedPolygon('C108_1') Or  IsNamedPolygon('SIGNAL_LAYER_4_C102_1_P038') Or  IsNamedPolygon('C108_1') Or  IsNamedPolygon('TOP_LAYER_54V2_P048') Or  IsNamedPolygon('TOP_LAYER_54V2_P048') Or  IsNamedPolygon('C108_1') Or  IsNamedPolygon('C108_1') Or  IsNamedPolygon('C108_1') Or  IsNamedPolygon('BOTTOM_LAYER_NETC106_2_P030') Or  IsNamedPolygon('SIGNAL_LAYER_1_IOUT_SNS_P044') Or  IsNamedPolygon('C108_1') Or  IsNamedPolygon('C102_1') Or  IsNamedPolygon('SIGNAL_LAYER_2_C102_1_P032') Or  IsNamedPolygon('BOTTOM_LAYER_54V1_P128')] p47: connectstyle=Direct reliefconductorwidth=0.254 reliefentries=4 polygonreliefangle="90 Angle" airgapwidth=0.254
PolygonConnect PolygonConnect_12 [All vs IsNamedPolygon('TOP_LAYER_54V2_P048')] p48: connectstyle=Direct reliefconductorwidth=0.254 reliefentries=4 polygonreliefangle="90 Angle" airgapwidth=0.254
PolygonConnect PolygonConnect_11 [All vs IsNamedPolygon('BOTTOM_LAYER_54V1_P128')] p49: connectstyle=Direct reliefconductorwidth=0.254 reliefentries=4 polygonreliefangle="90 Angle" airgapwidth=0.254
PolygonConnect PolygonConnect_10 [All vs IsNamedPolygon('SIGNAL_LAYER_1_IOUT_SNS_P044')] p50: thpad.connectstyle=Direct thpad.reliefconductorwidth=0.254 thpad.reliefentries=4 thpad.polygonreliefangle="90 Angle" thpad.airgapwidth=0.254 smdpad.connectstyle=Relief smdpad.reliefconductorwidth=0.254 smdpad.reliefentries=4 smdpad.polygonreliefangle="90 Angle" smdpad.airgapwidth=0.254 via.connectstyle=Direct via.reliefconductorwidth=0.254 via.reliefentries=4 via.polygonreliefangle="90 Angle" via.airgapwidth=0.254
PolygonConnect PolygonConnect_9 [All vs IsNamedPolygon('SGND')] p51: thpad.connectstyle=Direct thpad.reliefconductorwidth=0.254 thpad.reliefentries=4 thpad.polygonreliefangle="90 Angle" thpad.airgapwidth=0.254 smdpad.connectstyle=Relief smdpad.reliefconductorwidth=0.254 smdpad.reliefentries=4 smdpad.polygonreliefangle="90 Angle" smdpad.airgapwidth=0.254 via.connectstyle=Direct via.reliefconductorwidth=0.254 via.reliefentries=4 via.polygonreliefangle="90 Angle" via.airgapwidth=0.254
PolygonConnect PolygonConnect_8 [All vs IsNamedPolygon('SGND')] p52: thpad.connectstyle=Direct thpad.reliefconductorwidth=0.254 thpad.reliefentries=4 thpad.polygonreliefangle="90 Angle" thpad.airgapwidth=0.254 smdpad.connectstyle=Relief smdpad.reliefconductorwidth=0.254 smdpad.reliefentries=4 smdpad.polygonreliefangle="90 Angle" smdpad.airgapwidth=0.254 via.connectstyle=Direct via.reliefconductorwidth=0.254 via.reliefentries=4 via.polygonreliefangle="90 Angle" via.airgapwidth=0.254
PolygonConnect PolygonConnect_7 [All vs IsNamedPolygon('SGND')] p53: thpad.connectstyle=Relief thpad.reliefconductorwidth=0 thpad.reliefentries=4 thpad.polygonreliefangle="90 Angle" thpad.airgapwidth=0 smdpad.connectstyle=Relief smdpad.reliefconductorwidth=0.254 smdpad.reliefentries=4 smdpad.polygonreliefangle="90 Angle" smdpad.airgapwidth=0.254 via.connectstyle=Relief via.reliefconductorwidth=0.254 via.reliefentries=4 via.polygonreliefangle="90 Angle" via.airgapwidth=0.254
PolygonConnect PolygonConnect_6 [All vs IsNamedPolygon('SGND')] p54: thpad.connectstyle=Direct thpad.reliefconductorwidth=0.254 thpad.reliefentries=4 thpad.polygonreliefangle="90 Angle" thpad.airgapwidth=0.254 smdpad.connectstyle=Relief smdpad.reliefconductorwidth=0.254 smdpad.reliefentries=4 smdpad.polygonreliefangle="90 Angle" smdpad.airgapwidth=0.254 via.connectstyle=Relief via.reliefconductorwidth=0.254 via.reliefentries=4 via.polygonreliefangle="90 Angle" via.airgapwidth=0.254
PolygonConnect PolygonConnect_5 [All vs IsNamedPolygon('SGND')] p55: thpad.connectstyle=Direct thpad.reliefconductorwidth=0.254 thpad.reliefentries=4 thpad.polygonreliefangle="90 Angle" thpad.airgapwidth=0.254 smdpad.connectstyle=Relief smdpad.reliefconductorwidth=0.254 smdpad.reliefentries=4 smdpad.polygonreliefangle="90 Angle" smdpad.airgapwidth=0.254 via.connectstyle=Relief via.reliefconductorwidth=0.254 via.reliefentries=4 via.polygonreliefangle="90 Angle" via.airgapwidth=0.254
PolygonConnect PolygonConnect_4 [All vs IsNamedPolygon('SIGNAL_LAYER_1_PGND_P018') Or  IsNamedPolygon('SWNODE') Or  IsNamedPolygon('D403_2') Or  IsNamedPolygon('SIGNAL_LAYER_4_C102_1_P038') Or  IsNamedPolygon('D403_2') Or  IsNamedPolygon('BOTTOM_LAYER_NETC106_2_P030') Or  IsNamedPolygon('C102_1') Or  IsNamedPolygon('PGND') Or  IsNamedPolygon('SIGNAL_LAYER_2_C102_1_P032')] p56: connectstyle=Direct reliefconductorwidth=0.254 reliefentries=4 polygonreliefangle="90 Angle" airgapwidth=0.254
PolygonConnect PolygonConnect_3 [All vs IsNamedPolygon('SWNODE') Or  IsNamedPolygon('D403_2') Or  IsNamedPolygon('Neutral') Or  IsNamedPolygon('C106_2') Or  IsNamedPolygon('D403_2') Or  IsNamedPolygon('Neutral') Or  IsNamedPolygon('Neutral')] p57: connectstyle=Direct reliefconductorwidth=0.254 reliefentries=4 polygonreliefangle="90 Angle" airgapwidth=0.254
PolygonConnect PolygonConnect_2 [All vs IsNamedPolygon('Neutral') Or  IsNamedPolygon('Neutral') Or  IsNamedPolygon('C106_2') Or  IsNamedPolygon('SWNODE') Or  IsNamedPolygon('Neutral')] p58: connectstyle=Direct reliefconductorwidth=0.254 reliefentries=4 polygonreliefangle="90 Angle" airgapwidth=0.254
PolygonConnect PolygonConnect_1 [All vs IsNamedPolygon('Neutral') Or  IsNamedPolygon('Neutral')] p59: connectstyle=Direct reliefconductorwidth=0.254 reliefentries=4 polygonreliefangle="90 Angle" airgapwidth=0.254
PolygonConnect [All] p60: connectstyle=Direct reliefconductorwidth=0.254 reliefentries=4 polygonreliefangle="90 Angle" airgapwidth=0.254
RoutingVias ThermalPadVias [IsVia and InAnyComponent] p1: holewidth=0.2 width=0.5 viastyle="Through Hole" minholewidth=0.2 minwidth=0.5 maxholewidth=0.33 maxwidth=0.6
RoutingVias [All] p2: holewidth=0.254 width=0.864 viastyle="Through Hole" minholewidth=0.2 minwidth=0.483 maxholewidth=1.016 maxwidth=1.651
SilkToSilkClearance SilkToSilkClearance_Pb-FreeLogo [(HasFootprint('Pb-Free_Overlay_Medium') OR HasFootprint('Pb-Free_Overlay_Small')) vs (HasFootprint('Pb-Free_Overlay_Medium') OR HasFootprint('Pb-Free_Overlay_Small'))] p1: silktosilkclearance=0
SilkToSilkClearance [All] p2: silktosilkclearance=0.025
